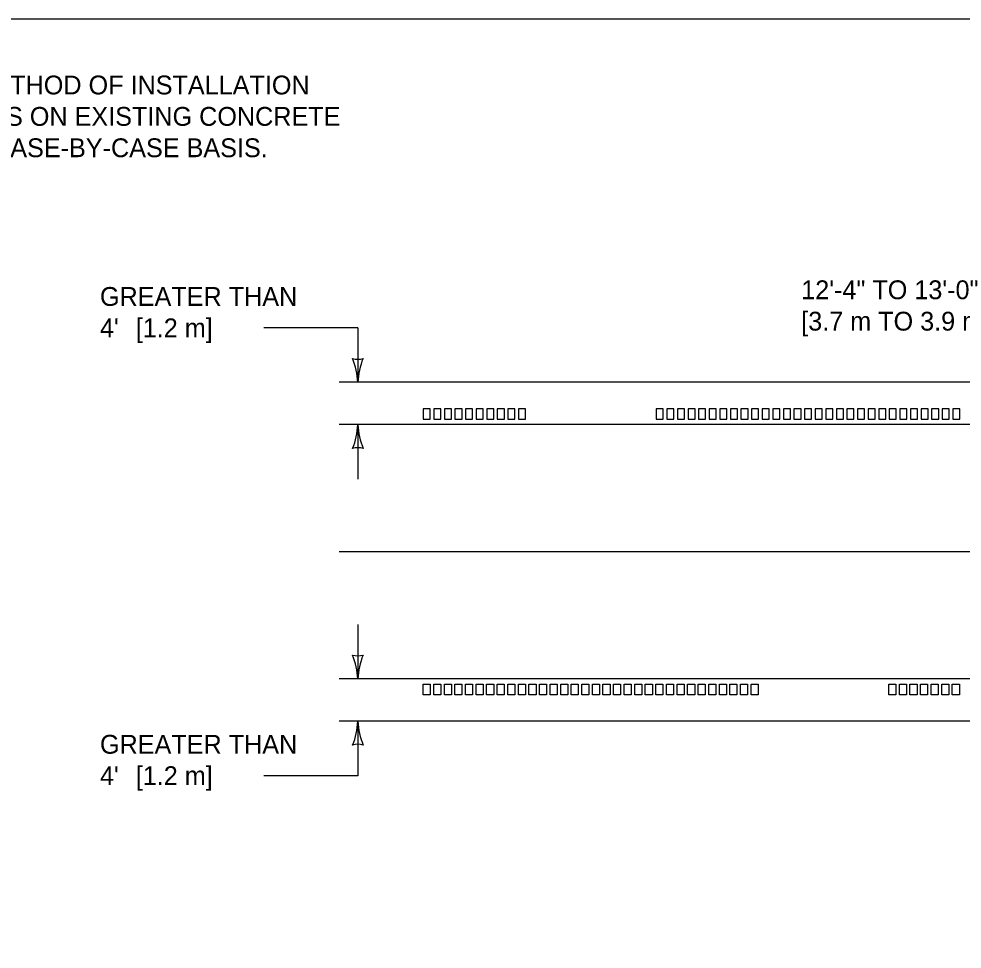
# Model space of a CAD drawing. Extents: x 49991.4 to 50021, y 49987.6 to 50011.4.
# Drawn here: x 50004.085 to 50007.091, y 49996.035 to 49998.999 of the extents above; entities that cross this region are included whole.
import ezdxf

# ---------------------------------------------------------------- set-up
doc = ezdxf.new("R2010")
doc.units = 0
for name, color, linetype in [('Level 1', 7, 'Continuous'), ('Level 2', 7, 'Continuous'), ('Level 3', 7, 'Continuous')]:
    doc.layers.add(name, color=color, linetype=linetype)

msp = doc.modelspace()

# ---------------------------------------------------------------- linework, layer by layer
at = {"layer": 'Level 1'}
for p, q in [((50011.3288, 49997.8413), (50005.1053, 49997.8413)), ((50011.3288, 49997.7063), (50005.1053, 49997.7063)), ((50011.3288, 49997.3013), (50005.1053, 49997.3013)), ((50011.3288, 49996.8963), (50005.1053, 49996.8963)), ((50007.3676, 49996.7613), (50005.1053, 49996.7613))]:
    msp.add_line(p, q, dxfattribs=at)
for points in [[(49999.3835, 49998.9992), (50016.7501, 49998.9992), (50016.7501, 49987.7988), (49999.3835, 49987.7988)], [(50005.3735, 49997.7235), (50005.396, 49997.7235), (50005.396, 49997.7572), (50005.3735, 49997.7572)], [(50005.4073, 49997.7235), (50005.4297, 49997.7235), (50005.4297, 49997.7572), (50005.4073, 49997.7572)], [(50005.441, 49997.7235), (50005.4635, 49997.7235), (50005.4635, 49997.7572), (50005.441, 49997.7572)], [(50005.4747, 49997.7235), (50005.4973, 49997.7235), (50005.4973, 49997.7572), (50005.4747, 49997.7572)], [(50005.5085, 49997.7235), (50005.531, 49997.7235), (50005.531, 49997.7572), (50005.5085, 49997.7572)], [(50005.5423, 49997.7235), (50005.5647, 49997.7235), (50005.5647, 49997.7572), (50005.5423, 49997.7572)], [(50005.576, 49997.7235), (50005.5985, 49997.7235), (50005.5985, 49997.7572), (50005.576, 49997.7572)], [(50005.6097, 49997.7235), (50005.6323, 49997.7235), (50005.6323, 49997.7572), (50005.6097, 49997.7572)], [(50005.6435, 49997.7235), (50005.666, 49997.7235), (50005.666, 49997.7572), (50005.6435, 49997.7572)], [(50005.6773, 49997.7235), (50005.6997, 49997.7235), (50005.6997, 49997.7572), (50005.6773, 49997.7572)], [(50006.1161, 49997.7235), (50006.1385, 49997.7235), (50006.1385, 49997.7572), (50006.1161, 49997.7572)], [(50006.1499, 49997.7235), (50006.1723, 49997.7235), (50006.1723, 49997.7572), (50006.1499, 49997.7572)], [(50006.1836, 49997.7235), (50006.206, 49997.7235), (50006.206, 49997.7572), (50006.1836, 49997.7572)], [(50006.2173, 49997.7235), (50006.2397, 49997.7235), (50006.2397, 49997.7572), (50006.2173, 49997.7572)], [(50006.2511, 49997.7235), (50006.2735, 49997.7235), (50006.2735, 49997.7572), (50006.2511, 49997.7572)], [(50006.2849, 49997.7235), (50006.3073, 49997.7235), (50006.3073, 49997.7572), (50006.2849, 49997.7572)], [(50006.3186, 49997.7235), (50006.341, 49997.7235), (50006.341, 49997.7572), (50006.3186, 49997.7572)], [(50006.3523, 49997.7235), (50006.3747, 49997.7235), (50006.3747, 49997.7572), (50006.3523, 49997.7572)], [(50006.3861, 49997.7235), (50006.4085, 49997.7235), (50006.4085, 49997.7572), (50006.3861, 49997.7572)], [(50006.4199, 49997.7235), (50006.4423, 49997.7235), (50006.4423, 49997.7572), (50006.4199, 49997.7572)], [(50006.4536, 49997.7235), (50006.476, 49997.7235), (50006.476, 49997.7572), (50006.4536, 49997.7572)], [(50006.4873, 49997.7235), (50006.5097, 49997.7235), (50006.5097, 49997.7572), (50006.4873, 49997.7572)], [(50006.5211, 49997.7235), (50006.5435, 49997.7235), (50006.5435, 49997.7572), (50006.5211, 49997.7572)], [(50006.5549, 49997.7235), (50006.5773, 49997.7235), (50006.5773, 49997.7572), (50006.5549, 49997.7572)], [(50006.5886, 49997.7235), (50006.611, 49997.7235), (50006.611, 49997.7572), (50006.5886, 49997.7572)], [(50006.6223, 49997.7235), (50006.6447, 49997.7235), (50006.6447, 49997.7572), (50006.6223, 49997.7572)], [(50006.6561, 49997.7235), (50006.6785, 49997.7235), (50006.6785, 49997.7572), (50006.6561, 49997.7572)], [(50006.6899, 49997.7235), (50006.7123, 49997.7235), (50006.7123, 49997.7572), (50006.6899, 49997.7572)], [(50006.7236, 49997.7235), (50006.746, 49997.7235), (50006.746, 49997.7572), (50006.7236, 49997.7572)], [(50006.7573, 49997.7235), (50006.7797, 49997.7235), (50006.7797, 49997.7572), (50006.7573, 49997.7572)], [(50006.7911, 49997.7235), (50006.8135, 49997.7235), (50006.8135, 49997.7572), (50006.7911, 49997.7572)], [(50006.8249, 49997.7235), (50006.8473, 49997.7235), (50006.8473, 49997.7572), (50006.8249, 49997.7572)], [(50006.8586, 49997.7235), (50006.881, 49997.7235), (50006.881, 49997.7572), (50006.8586, 49997.7572)], [(50006.8923, 49997.7235), (50006.9147, 49997.7235), (50006.9147, 49997.7572), (50006.8923, 49997.7572)], [(50006.9261, 49997.7235), (50006.9485, 49997.7235), (50006.9485, 49997.7572), (50006.9261, 49997.7572)], [(50006.9599, 49997.7235), (50006.9823, 49997.7235), (50006.9823, 49997.7572), (50006.9599, 49997.7572)], [(50006.9936, 49997.7235), (50007.016, 49997.7235), (50007.016, 49997.7572), (50006.9936, 49997.7572)], [(50007.0273, 49997.7235), (50007.0497, 49997.7235), (50007.0497, 49997.7572), (50007.0273, 49997.7572)], [(50007.0611, 49997.7235), (50007.0835, 49997.7235), (50007.0835, 49997.7572), (50007.0611, 49997.7572)], [(50005.3735, 49996.8792), (50005.396, 49996.8792), (50005.396, 49996.8455), (50005.3735, 49996.8455)], [(50005.4072, 49996.8792), (50005.4297, 49996.8792), (50005.4297, 49996.8455), (50005.4072, 49996.8455)], [(50005.4409, 49996.8792), (50005.4634, 49996.8792), (50005.4634, 49996.8455), (50005.4409, 49996.8455)], [(50005.4746, 49996.8792), (50005.4971, 49996.8792), (50005.4971, 49996.8455), (50005.4746, 49996.8455)], [(50005.5083, 49996.8792), (50005.5308, 49996.8792), (50005.5308, 49996.8455), (50005.5083, 49996.8455)], [(50005.542, 49996.8792), (50005.5645, 49996.8792), (50005.5645, 49996.8455), (50005.542, 49996.8455)], [(50005.5757, 49996.8792), (50005.5982, 49996.8792), (50005.5982, 49996.8455), (50005.5757, 49996.8455)], [(50005.6094, 49996.8792), (50005.6319, 49996.8792), (50005.6319, 49996.8455), (50005.6094, 49996.8455)], [(50005.6431, 49996.8792), (50005.6656, 49996.8792), (50005.6656, 49996.8455), (50005.6431, 49996.8455)], [(50005.6768, 49996.8792), (50005.6993, 49996.8792), (50005.6993, 49996.8455), (50005.6768, 49996.8455)], [(50005.7105, 49996.8792), (50005.733, 49996.8792), (50005.733, 49996.8455), (50005.7105, 49996.8455)], [(50005.7442, 49996.8792), (50005.7667, 49996.8792), (50005.7667, 49996.8455), (50005.7442, 49996.8455)], [(50005.7779, 49996.8792), (50005.8004, 49996.8792), (50005.8004, 49996.8455), (50005.7779, 49996.8455)], [(50005.8116, 49996.8792), (50005.8341, 49996.8792), (50005.8341, 49996.8455), (50005.8116, 49996.8455)], [(50005.8453, 49996.8792), (50005.8678, 49996.8792), (50005.8678, 49996.8455), (50005.8453, 49996.8455)], [(50005.879, 49996.8792), (50005.9015, 49996.8792), (50005.9015, 49996.8455), (50005.879, 49996.8455)], [(50005.9127, 49996.8792), (50005.9352, 49996.8792), (50005.9352, 49996.8455), (50005.9127, 49996.8455)], [(50005.9464, 49996.8792), (50005.9689, 49996.8792), (50005.9689, 49996.8455), (50005.9464, 49996.8455)], [(50005.9801, 49996.8792), (50006.0026, 49996.8792), (50006.0026, 49996.8455), (50005.9801, 49996.8455)], [(50006.0138, 49996.8792), (50006.0363, 49996.8792), (50006.0363, 49996.8455), (50006.0138, 49996.8455)], [(50006.0475, 49996.8792), (50006.07, 49996.8792), (50006.07, 49996.8455), (50006.0475, 49996.8455)], [(50006.0812, 49996.8792), (50006.1037, 49996.8792), (50006.1037, 49996.8455), (50006.0812, 49996.8455)], [(50006.1149, 49996.8792), (50006.1374, 49996.8792), (50006.1374, 49996.8455), (50006.1149, 49996.8455)], [(50006.1486, 49996.8792), (50006.1711, 49996.8792), (50006.1711, 49996.8455), (50006.1486, 49996.8455)], [(50006.1823, 49996.8792), (50006.2048, 49996.8792), (50006.2048, 49996.8455), (50006.1823, 49996.8455)], [(50006.216, 49996.8792), (50006.2385, 49996.8792), (50006.2385, 49996.8455), (50006.216, 49996.8455)], [(50006.2497, 49996.8792), (50006.2722, 49996.8792), (50006.2722, 49996.8455), (50006.2497, 49996.8455)], [(50006.2834, 49996.8792), (50006.3059, 49996.8792), (50006.3059, 49996.8455), (50006.2834, 49996.8455)], [(50006.3171, 49996.8792), (50006.3396, 49996.8792), (50006.3396, 49996.8455), (50006.3171, 49996.8455)], [(50006.3508, 49996.8792), (50006.3733, 49996.8792), (50006.3733, 49996.8455), (50006.3508, 49996.8455)], [(50006.3845, 49996.8792), (50006.407, 49996.8792), (50006.407, 49996.8455), (50006.3845, 49996.8455)], [(50006.4182, 49996.8792), (50006.4407, 49996.8792), (50006.4407, 49996.8455), (50006.4182, 49996.8455)], [(50006.8571, 49996.8792), (50006.8796, 49996.8792), (50006.8796, 49996.8455), (50006.8571, 49996.8455)], [(50006.8908, 49996.8792), (50006.9133, 49996.8792), (50006.9133, 49996.8455), (50006.8908, 49996.8455)], [(50006.9245, 49996.8792), (50006.947, 49996.8792), (50006.947, 49996.8455), (50006.9245, 49996.8455)], [(50006.9582, 49996.8792), (50006.9807, 49996.8792), (50006.9807, 49996.8455), (50006.9582, 49996.8455)], [(50006.9919, 49996.8792), (50007.0144, 49996.8792), (50007.0144, 49996.8455), (50006.9919, 49996.8455)], [(50007.0256, 49996.8792), (50007.0481, 49996.8792), (50007.0481, 49996.8455), (50007.0256, 49996.8455)], [(50007.0593, 49996.8792), (50007.0818, 49996.8792), (50007.0818, 49996.8455), (50007.0593, 49996.8455)]]:
    msp.add_lwpolyline(points, close=True, dxfattribs=at)
at = {"layer": 'Level 3'}
for p, q in [((50005.1653, 49998.0147), (50004.8653, 49998.0147)), ((50005.1653, 49998.0147), (50005.1653, 49997.8413)), ((50005.1653, 49997.7063), (50005.1653, 49997.5329)), ((50005.1653, 49997.0697), (50005.1653, 49996.8963)), ((50005.1653, 49996.7613), (50005.1653, 49996.5879)), ((50005.1653, 49996.5879), (50004.8653, 49996.5879))]:
    msp.add_line(p, q, dxfattribs=at)
for centre, radius, start, end in [((50005.1653, 49997.9695), 0.0548, 252.1388, 287.8612), ((50004.9326, 49997.8298), 0.233, 2.8273, 22.0772), ((50005.3874, 49997.8321), 0.2223, 157.456, 177.6395), ((50004.9432, 49997.7155), 0.2223, 337.456, 357.6395), ((50005.398, 49997.7178), 0.233, 182.8273, 202.0772), ((50005.1653, 49997.5781), 0.0548, 72.1388, 107.8612), ((50005.1653, 49997.0245), 0.0548, 252.1388, 287.8612), ((50004.9326, 49996.8848), 0.233, 2.8273, 22.0772), ((50005.3874, 49996.8871), 0.2223, 157.456, 177.6395), ((50004.9432, 49996.7705), 0.2223, 337.456, 357.6395), ((50005.398, 49996.7728), 0.233, 182.8273, 202.0772), ((50005.1653, 49996.6331), 0.0548, 72.1388, 107.8612)]:
    msp.add_arc(centre, radius, start, end, dxfattribs=at)

# ---------------------------------------------------------------- texts
at = {"layer": 'Level 2'}
for s, p in [('DETERMINE THE METHOD OF INSTALLATION', (50003.2598, 49998.7585)), ('FOR RUMBLE STRIPS ON EXISTING CONCRETE', (50003.2598, 49998.6585)), ('SHOULDERS ON A CASE-BY-CASE BASIS.', (50003.2598, 49998.5585)), ('12\'-4" TO 13\'-0"', (50006.578, 49998.106)), ('[3.7 m TO 3.9 m] GAP', (50006.578, 49998.006))]:
    msp.add_text(s, height=0.06, dxfattribs=at).set_placement(p)
for s, p in [('GREATER THAN', (50004.3437, 49998.0847)), ('[1.2 m] ', (50004.4577, 49997.9847)), ("4' ", (50004.3437, 49997.9847)), ('GREATER THAN', (50004.3437, 49996.6579)), ("4' ", (50004.3437, 49996.5579)), ('[1.2 m] ', (50004.4577, 49996.5579))]:
    msp.add_text(s, height=0.06, rotation=0.0001, dxfattribs=at).set_placement(p)

doc.saveas('drawing.dxf')
